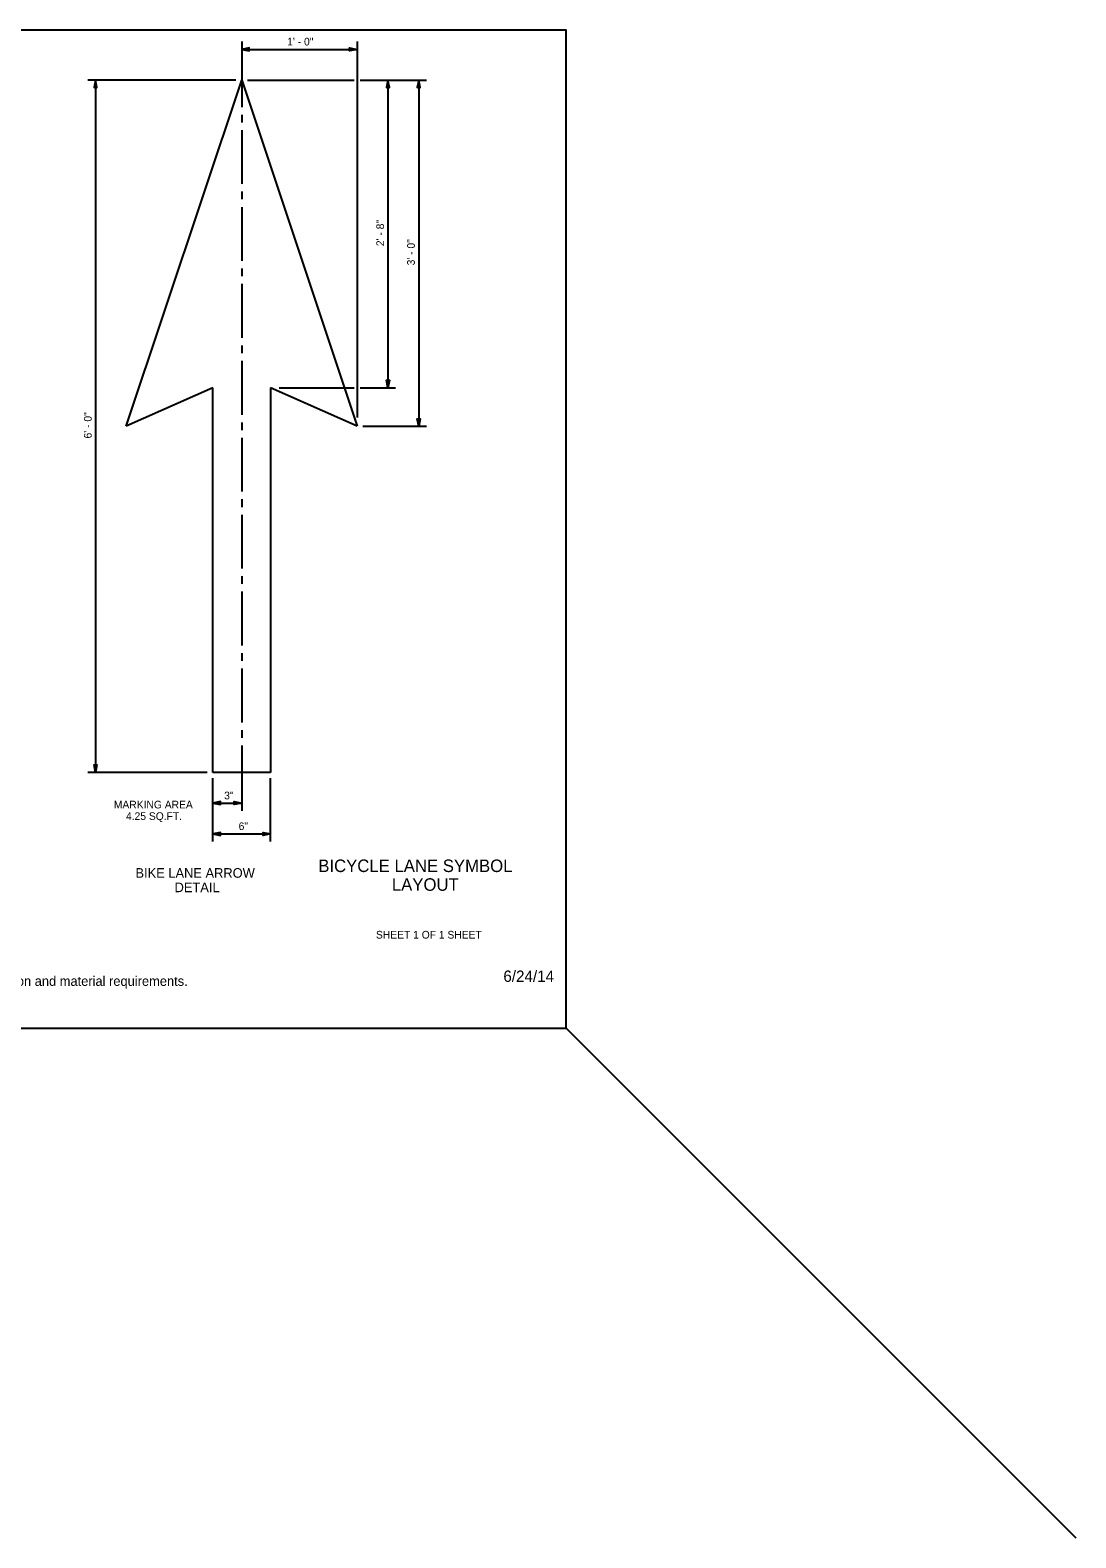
# Model space of a CAD drawing. Extents: x 99862 to 104211, y 98939 to 102076.
# Drawn here: x 102036 to 104211, y 98939 to 102076 of the extents above; entities that cross this region are included whole.
import ezdxf

# ---------------------------------------------------------------- set-up
doc = ezdxf.new("R2010")
doc.units = 0
for name, color, linetype in [('Level 1', 7, 'Continuous'), ('Level 15', 7, 'Continuous'), ('Level 20', 7, 'Continuous'), ('Level 60', 7, 'Continuous'), ('Level 62', 7, 'Continuous'), ('Level 7', 7, 'Continuous')]:
    doc.layers.add(name, color=color, linetype=linetype)

msp = doc.modelspace()

# ---------------------------------------------------------------- linework, layer by layer
at = {"layer": 'Level 1'}
msp.add_line((103150, 100000), (104210.7, 98939.3), dxfattribs=at)
msp.add_lwpolyline([(99862, 99999.5), (103151, 99999.5), (103151, 102075.5), (99862, 102075.5)], close=True, dxfattribs=at)
at = {"layer": 'Level 15'}
for p, q in [((102476.2, 102051.6), (102476.2, 101915.6)), ((102716.2, 102051.6), (102716.2, 101269.6)), ((102476.2, 102035.6), (102716.2, 102035.6)), ((102464.2, 101971.6), (102156.2, 101971.6)), ((102172.2, 101971.6), (102172.2, 100531.6)), ((102488.2, 101971.6), (102710.2, 101971.6)), ((102722.2, 101971.6), (102860.2, 101971.6)), ((102780.2, 101971.6), (102780.2, 101331.6)), ((102844.2, 101971.6), (102844.2, 101251.6)), ((102476.2, 101899.6), (102476.2, 101883.6)), ((102476.2, 101867.6), (102476.2, 101755.6)), ((102476.2, 101739.6), (102476.2, 101723.6)), ((102476.2, 101707.6), (102476.2, 101595.6)), ((102476.2, 101579.6), (102476.2, 101563.6)), ((102476.2, 101547.6), (102476.2, 101435.6)), ((102476.2, 101419.6), (102476.2, 101403.6)), ((102476.2, 101387.6), (102476.2, 101275.6)), ((102554.2, 101331.6), (102710.2, 101331.6)), ((102722.2, 101331.6), (102796.2, 101331.6)), ((102476.2, 101259.6), (102476.2, 101243.6)), ((102728.2, 101251.6), (102860.2, 101251.6)), ((102476.2, 101227.6), (102476.2, 101115.6)), ((102476.2, 101099.6), (102476.2, 101083.6)), ((102476.2, 101067.6), (102476.2, 100955.6)), ((102476.2, 100939.6), (102476.2, 100923.6)), ((102476.2, 100907.6), (102476.2, 100795.6)), ((102476.2, 100779.6), (102476.2, 100763.6)), ((102476.2, 100747.6), (102476.2, 100635.6)), ((102476.2, 100619.6), (102476.2, 100603.6)), ((102476.2, 100587.6), (102476.2, 100451.6)), ((102404.2, 100531.6), (102156.2, 100531.6)), ((102416.2, 100387.6), (102416.2, 100519.6)), ((102536.2, 100387.6), (102536.2, 100519.6)), ((102416.2, 100467.6), (102476.2, 100467.6)), ((102416.2, 100403.6), (102536.2, 100403.6))]:
    msp.add_line(p, q, dxfattribs=at)
for points in [[(102476.2, 102035.6), (102491.9, 102032.5), (102491.2, 102035.6), (102491.9, 102038.7)], [(102716.2, 102035.6), (102700.5, 102032.5), (102701.2, 102035.6), (102700.5, 102038.7)], [(102172.2, 101971.6), (102169.1, 101955.9), (102172.2, 101956.6), (102175.3, 101955.9)], [(102780.2, 101971.6), (102777.1, 101955.9), (102780.2, 101956.6), (102783.3, 101955.9)], [(102844.2, 101971.6), (102841.1, 101955.9), (102844.2, 101956.6), (102847.3, 101955.9)], [(102780.2, 101331.6), (102777.1, 101347.3), (102780.2, 101346.6), (102783.3, 101347.3)], [(102844.2, 101251.6), (102841.1, 101267.3), (102844.2, 101266.6), (102847.3, 101267.3)], [(102172.2, 100531.6), (102169.1, 100547.3), (102172.2, 100546.6), (102175.3, 100547.3)], [(102416.2, 100467.6), (102431.9, 100464.5), (102431.2, 100467.6), (102431.9, 100470.7)], [(102476.2, 100467.6), (102460.5, 100464.5), (102461.2, 100467.6), (102460.5, 100470.7)], [(102416.2, 100403.6), (102431.9, 100400.5), (102431.2, 100403.6), (102431.9, 100406.7)], [(102536.2, 100403.6), (102520.5, 100400.5), (102521.2, 100403.6), (102520.5, 100406.7)]]:
    msp.add_lwpolyline(points, close=True, dxfattribs=at)
at = {"layer": 'Level 60'}
msp.add_line((103151, 102075.5), (103151, 102075.5), dxfattribs=at)
at = {"layer": 'Level 7'}
for p, q in [((102236.2, 101251.6), (102476.2, 101971.6)), ((102476.2, 101971.6), (102716.2, 101251.6)), ((102416.2, 101331.6), (102236.2, 101251.6)), ((102416.2, 100531.6), (102416.2, 101331.6)), ((102716.2, 101251.6), (102536.2, 101331.6)), ((102536.2, 101331.6), (102536.2, 100531.6)), ((102536.2, 100531.6), (102416.2, 100531.6))]:
    msp.add_line(p, q, dxfattribs=at)

# ---------------------------------------------------------------- texts
at = {"layer": 'Level 1'}
msp.add_text('6/24/14', height=23.62, dxfattribs=at).set_placement((103020.3, 100095.8))
at = {"layer": 'Level 20'}
for s, height, p in [('1\' - 0"', 16, (102570.8, 102043.6)), ('3"', 16, (102439.8, 100475.6)), ('MARKING AREA', 16, (102210.4, 100456.6)), ('4.25 SQ.FT.', 16, (102235.6, 100432.6)), ('6"', 16, (102469.8, 100411.6)), ('See Contract for location and material requirements.', 20, (101744, 100087.5))]:
    msp.add_text(s, height=height, dxfattribs=at).set_placement(p)
for s, height, rotation, p in [('2\' - 8"', 16, 90, (102772.2, 101626.2)), ('3\' - 0"', 16, 90, (102836.2, 101586.2)), ('6\' - 0"', 16, 90, (102164.2, 101226.2)), ('BIKE LANE ARROW', 20, 360, (102255.3, 100312.4)), ('DETAIL', 20, 360, (102336.6, 100282.4))]:
    msp.add_text(s, height=height, rotation=rotation, dxfattribs=at).set_placement(p)
at = {"layer": 'Level 62'}
for s, height, p in [('BICYCLE LANE SYMBOL', 26, (102635.4, 100324.3)), ('LAYOUT', 26, (102788.4, 100285.3)), ('SHEET 1 OF 1 SHEET', 16, (102755.4, 100185.9))]:
    msp.add_text(s, height=height, dxfattribs=at).set_placement(p)

doc.saveas('drawing.dxf')
